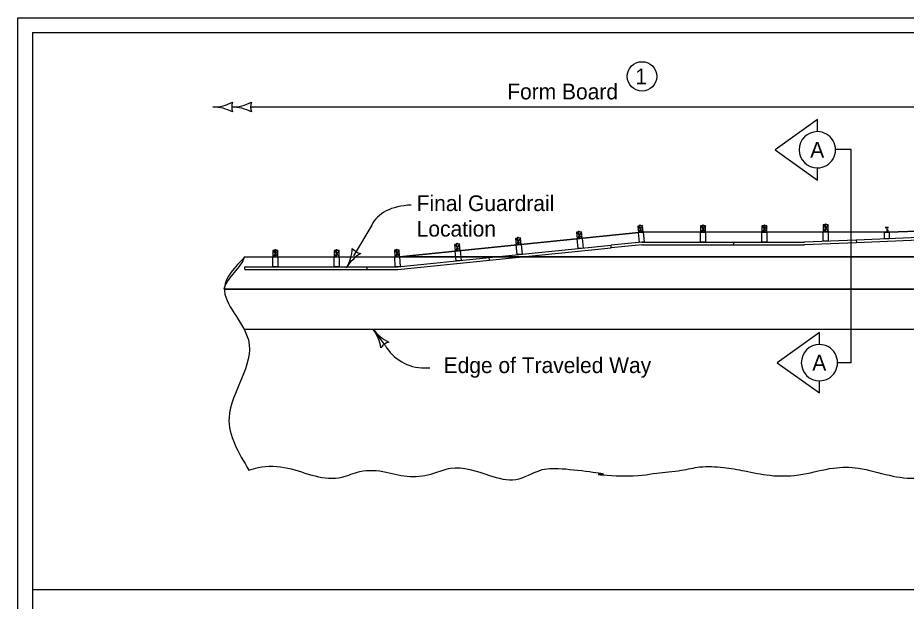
# Model space of a CAD drawing. Extents: x 9538 to 81668, y 7600 to 11751.
# Drawn here: x 17333 to 18239, y 9349 to 9944 of the extents above; entities that cross this region are included whole.
import ezdxf

# ---------------------------------------------------------------- set-up
doc = ezdxf.new("R2010")
doc.units = 0
for name, color, linetype in [('Default', 7, 'Continuous'), ('DsnShtMinorGrid13', 7, 'Continuous'), ('DsnShtMinorGrid14', 7, 'Continuous'), ('dsnStdCells', 7, 'Continuous'), ('dsnStdDimension', 7, 'Continuous'), ('dsnStdNameDate', 7, 'Continuous'), ('dsnStdNote', 7, 'Continuous'), ('dsnStdPattern', 7, 'Continuous'), ('dsnStdShading', 7, 'Continuous'), ('dsnStdTable', 7, 'Continuous')]:
    doc.layers.add(name, color=color, linetype=linetype)

msp = doc.modelspace()

# ---------------------------------------------------------------- linework, layer by layer
at = {"layer": 'Default'}
msp.add_lwpolyline([(17332.53, 9944.02), (20467.54, 9944.02), (20467.54, 7924.02), (17332.53, 7924.02)], close=True, dxfattribs=at)
at = {"layer": 'DsnShtMinorGrid13'}
msp.add_circle((17969.21, 9884.28), 15, dxfattribs=at)
at = {"layer": 'DsnShtMinorGrid14'}
for p, q in [((17969.82, 9732.2), (17965.51, 9725.07)), ((17967.24, 9732.92), (17967.23, 9732.99)), ((18031.5, 9733), (18031.5, 9733.07)), ((18094, 9733), (18094, 9733.07)), ((18154, 9732.89), (18159, 9726.23)), ((18159, 9732.89), (18154, 9726.23)), ((18156.5, 9733.86), (18156.5, 9733.93)), ((18156.5, 9726.23), (18156.5, 9732.89)), ((17902.38, 9725.42), (17908.03, 9719.29)), ((17907.36, 9725.92), (17903.05, 9718.79)), ((17904.77, 9726.64), (17904.77, 9726.71)), ((17905.54, 9719.04), (17904.87, 9725.67)), ((17964.85, 9731.7), (17970.49, 9725.56)), ((17965.51, 9725.07), (17970.49, 9725.56)), ((17968, 9725.32), (17965.51, 9725.07)), ((17968, 9725.32), (17965.51, 9725.07)), ((17966.51, 9715.11), (17965.51, 9725.07)), ((17968, 9725.32), (17967.34, 9731.95)), ((17970.49, 9725.56), (17971.49, 9715.61)), ((18029, 9732.03), (18034, 9725.37)), ((18034, 9732.03), (18029, 9725.37)), ((18029, 9725.37), (18034, 9725.37)), ((18029, 9715.36), (18029, 9725.37)), ((18031.5, 9725.37), (18031.5, 9732.03)), ((18034, 9725.37), (18034, 9715.36)), ((18091.5, 9732.03), (18096.5, 9725.37)), ((18096.5, 9732.03), (18091.5, 9725.37)), ((18091.5, 9725.37), (18096.5, 9725.37)), ((18091.5, 9715.36), (18091.5, 9725.37)), ((18094, 9725.37), (18094, 9732.03)), ((18096.5, 9725.37), (18096.5, 9715.36)), ((18154, 9726.23), (18159, 9726.23)), ((18154, 9716.22), (18154, 9726.23)), ((18159, 9726.23), (18159, 9716.22)), ((17780.41, 9714.18), (17780.4, 9714.25)), ((17840.2, 9719.17), (17845.84, 9713.04)), ((17845.17, 9719.67), (17840.86, 9712.54)), ((17842.59, 9720.39), (17842.58, 9720.46)), ((17843.35, 9712.79), (17842.68, 9719.42)), ((17903.05, 9718.79), (17908.03, 9719.29)), ((17904.05, 9708.83), (17903.05, 9718.79)), ((17908.03, 9719.29), (17909.03, 9709.33)), ((17969, 9715.36), (17937.63, 9712.2)), ((17971.49, 9715.61), (17966.51, 9715.11)), ((17969, 9715.36), (18062.75, 9715.36)), ((18034, 9715.36), (18029, 9715.36)), ((18062.75, 9712.64), (18062.75, 9715.36)), ((18062.75, 9715.36), (18134.98, 9715.36)), ((18062.75, 9712.65), (18062.75, 9715.36)), ((18096.5, 9715.36), (18091.5, 9715.36)), ((18159, 9716.22), (18154, 9716.22)), ((17592.75, 9706.96), (17597.75, 9700.29)), ((17597.75, 9706.96), (17592.75, 9700.29)), ((17595.25, 9707.93), (17595.25, 9708)), ((17595.25, 9700.29), (17595.25, 9706.96)), ((17655.25, 9706.96), (17660.25, 9700.29)), ((17660.25, 9706.96), (17655.25, 9700.29)), ((17657.75, 9707.93), (17657.75, 9708)), ((17657.75, 9700.29), (17657.75, 9706.96)), ((17716.64, 9707.02), (17721.97, 9700.58)), ((17721.64, 9707.27), (17716.97, 9700.33)), ((17719.09, 9708.12), (17719.09, 9708.19)), ((17719.47, 9700.45), (17719.14, 9707.15)), ((17778.02, 9712.96), (17783.66, 9706.79)), ((17782.99, 9713.46), (17778.68, 9706.29)), ((17778.68, 9706.29), (17783.66, 9706.79)), ((17779.68, 9696.28), (17778.68, 9706.29)), ((17781.17, 9706.54), (17780.51, 9713.21)), ((17783.66, 9706.79), (17784.66, 9696.78)), ((17813.26, 9699.7), (17937.63, 9712.2)), ((17813.53, 9697.01), (17937.91, 9709.51)), ((17840.86, 9712.54), (17845.84, 9713.04)), ((17841.86, 9702.58), (17840.86, 9712.54)), ((17845.84, 9713.04), (17846.84, 9703.08)), ((17909.03, 9709.33), (17904.05, 9708.83)), ((17937.91, 9709.51), (17937.63, 9712.2)), ((17937.9, 9709.52), (17937.63, 9712.2)), ((17969, 9712.65), (17937.9, 9709.52)), ((17969, 9712.65), (18062.75, 9712.65)), ((18062.75, 9712.65), (18135.01, 9712.65)), ((17592.75, 9700.29), (17597.76, 9700.29)), ((17592.75, 9690.28), (17592.75, 9700.29)), ((17597.76, 9700.29), (17597.76, 9690.28)), ((17655.25, 9700.29), (17660.26, 9700.29)), ((17655.25, 9690.28), (17655.25, 9700.29)), ((17660.26, 9700.29), (17660.26, 9690.28)), ((17716.97, 9700.33), (17721.97, 9700.58)), ((17717.47, 9690.28), (17716.97, 9700.33)), ((17719.98, 9690.28), (17813.26, 9699.7)), ((17720.25, 9687.57), (17813.53, 9697)), ((17721.97, 9700.58), (17722.47, 9690.53)), ((17784.66, 9696.78), (17779.68, 9696.28)), ((17813.53, 9697), (17813.26, 9699.7)), ((17813.53, 9697.01), (17813.26, 9699.7)), ((17846.84, 9703.08), (17841.86, 9702.58)), ((17564, 9690.28), (17689, 9690.28)), ((17564, 9687.57), (17564, 9690.28)), ((17564, 9687.57), (17689, 9687.57)), ((17597.76, 9690.28), (17592.75, 9690.28)), ((17660.26, 9690.28), (17655.25, 9690.28)), ((17689, 9690.28), (17719.98, 9690.28)), ((17689, 9687.57), (17689, 9690.28)), ((17689, 9687.57), (17720.25, 9687.57)), ((17722.47, 9690.53), (17717.47, 9690.28))]:
    msp.add_line(p, q, dxfattribs=at)
for points in [[(17965.51, 9725.07), (17970.49, 9725.56), (17969.82, 9732.2), (17964.85, 9731.7)], [(18154, 9726.23), (18159, 9726.23), (18159, 9732.89), (18154, 9732.89)], [(17903.05, 9718.79), (17908.03, 9719.29), (17907.36, 9725.92), (17902.38, 9725.42)], [(18029, 9725.37), (18034, 9725.37), (18034, 9732.03), (18029, 9732.03)], [(18091.5, 9725.37), (18096.5, 9725.37), (18096.5, 9732.03), (18091.5, 9732.03)], [(17840.86, 9712.54), (17845.84, 9713.04), (17845.17, 9719.67), (17840.2, 9719.17)], [(17592.75, 9700.29), (17597.75, 9700.29), (17597.75, 9706.96), (17592.75, 9706.96)], [(17655.25, 9700.29), (17660.25, 9700.29), (17660.25, 9706.96), (17655.25, 9706.96)], [(17716.97, 9700.33), (17721.97, 9700.58), (17721.64, 9707.27), (17716.64, 9707.02)], [(17778.68, 9706.29), (17783.66, 9706.79), (17782.99, 9713.46), (17778.02, 9712.96)]]:
    msp.add_lwpolyline(points, close=True, dxfattribs=at)
for points in [[(17967, 9731.92), (17966.96, 9732.34), (17967.62, 9732.41), (17967.67, 9731.98)], [(17967.1, 9732.36), (17967.05, 9732.9), (17967.43, 9732.94), (17967.49, 9732.4)], [(18031.16, 9732.03), (18031.16, 9732.46), (18031.83, 9732.46), (18031.83, 9732.03)], [(18031.3, 9732.46), (18031.3, 9733), (18031.69, 9733), (18031.69, 9732.46)], [(18093.66, 9732.03), (18093.66, 9732.46), (18094.33, 9732.46), (18094.33, 9732.03)], [(18093.8, 9732.46), (18093.8, 9733), (18094.19, 9733), (18094.19, 9732.46)], [(18156.16, 9732.89), (18156.16, 9733.32), (18156.83, 9733.32), (18156.83, 9732.89)], [(18156.3, 9733.32), (18156.3, 9733.86), (18156.69, 9733.86), (18156.69, 9733.32)], [(17904.54, 9725.64), (17904.5, 9726.07), (17905.16, 9726.13), (17905.2, 9725.7)], [(17904.63, 9726.08), (17904.58, 9726.62), (17904.97, 9726.66), (17905.02, 9726.12)], [(17780.27, 9713.62), (17780.22, 9714.16), (17780.6, 9714.2), (17780.66, 9713.66)], [(17842.35, 9719.39), (17842.31, 9719.82), (17842.97, 9719.88), (17843.02, 9719.45)], [(17842.45, 9719.83), (17842.39, 9720.37), (17842.78, 9720.41), (17842.84, 9719.87)], [(17594.92, 9706.96), (17594.92, 9707.39), (17595.58, 9707.39), (17595.58, 9706.96)], [(17595.06, 9707.39), (17595.06, 9707.93), (17595.45, 9707.93), (17595.45, 9707.39)], [(17657.42, 9706.96), (17657.42, 9707.39), (17658.08, 9707.39), (17658.08, 9706.96)], [(17657.56, 9707.39), (17657.56, 9707.93), (17657.95, 9707.93), (17657.95, 9707.39)], [(17718.81, 9707.13), (17718.78, 9707.56), (17719.45, 9707.59), (17719.47, 9707.16)], [(17718.92, 9707.57), (17718.9, 9708.11), (17719.28, 9708.13), (17719.31, 9707.59)], [(17780.18, 9713.17), (17780.13, 9713.61), (17780.8, 9713.67), (17780.84, 9713.24)], [(17719.47, 9700.45), (17716.97, 9700.33), (17716.97, 9700.33)]]:
    msp.add_lwpolyline(points, dxfattribs=at)
at = {"layer": 'dsnStdCells'}
for p, q in [((18216.44, 9718.72), (18216.44, 9725.68)), ((18216.44, 9725.68), (18217.07, 9725.68)), ((18217.07, 9725.37), (18217.07, 9725.68)), ((18220.82, 9725.37), (18217.07, 9725.37)), ((18220.71, 9730.26), (18217.38, 9730.26)), ((18217.38, 9730.26), (18217.38, 9730.1)), ((18217.38, 9730.26), (18217.38, 9730.1)), ((18220.71, 9730.26), (18217.38, 9730.26)), ((18217.38, 9730.1), (18218.55, 9730.1)), ((18217.38, 9730.1), (18218.55, 9730.1)), ((18218.55, 9725.52), (18217.38, 9725.52)), ((18217.38, 9725.52), (18217.38, 9725.37)), ((18217.38, 9725.52), (18217.38, 9725.37)), ((18218.55, 9725.52), (18217.38, 9725.52)), ((18217.38, 9725.37), (18220.71, 9725.37)), ((18217.38, 9725.37), (18220.71, 9725.37)), ((18218.97, 9729.69), (18218.97, 9725.94)), ((18218.97, 9729.69), (18218.97, 9725.94)), ((18219.12, 9725.94), (18219.12, 9729.69)), ((18219.12, 9725.94), (18219.12, 9729.69)), ((18219.36, 9726.04), (18219.28, 9725.99)), ((18219.36, 9726.04), (18219.28, 9725.99)), ((18219.28, 9725.99), (18219.28, 9725.61)), ((18219.28, 9725.61), (18219.28, 9725.99)), ((18219.36, 9726.04), (18220.33, 9726.04)), ((18220.33, 9726.04), (18219.36, 9726.04)), ((18219.54, 9730.1), (18220.71, 9730.1)), ((18219.54, 9730.1), (18220.71, 9730.1)), ((18220.71, 9725.52), (18219.54, 9725.52)), ((18220.71, 9725.52), (18219.54, 9725.52)), ((18219.58, 9725.99), (18219.58, 9725.57)), ((18219.58, 9725.57), (18219.58, 9725.99)), ((18219.58, 9725.57), (18219.58, 9725.99)), ((18220.14, 9727.55), (18219.62, 9727.55)), ((18219.62, 9727.55), (18219.62, 9726.04)), ((18220.14, 9727.55), (18219.62, 9727.55)), ((18219.62, 9727.55), (18219.62, 9726.04)), ((18219.62, 9726.04), (18220.14, 9726.04)), ((18220.14, 9726.04), (18220.14, 9727.55)), ((18220.14, 9726.04), (18220.14, 9727.55)), ((18220.18, 9725.57), (18220.18, 9725.99)), ((18220.18, 9725.99), (18220.18, 9725.57)), ((18220.18, 9725.57), (18220.18, 9725.99)), ((18220.33, 9726.04), (18220.4, 9726.04)), ((18220.4, 9726.04), (18220.33, 9726.04)), ((18220.48, 9725.99), (18220.4, 9726.04)), ((18220.48, 9725.99), (18220.4, 9726.04)), ((18220.4, 9725.52), (18220.48, 9725.57)), ((18220.4, 9725.52), (18220.48, 9725.57)), ((18220.48, 9725.57), (18220.48, 9725.99)), ((18220.48, 9725.57), (18220.48, 9725.99)), ((18220.71, 9730.1), (18220.71, 9730.26)), ((18220.71, 9730.1), (18220.71, 9730.26)), ((18220.71, 9725.37), (18220.71, 9725.52)), ((18220.71, 9725.37), (18220.71, 9725.52)), ((18220.82, 9725.68), (18221.44, 9725.68)), ((18220.82, 9725.68), (18220.82, 9725.37)), ((18221.44, 9725.68), (18221.44, 9718.72)), ((18221.44, 9718.72), (18216.44, 9718.72))]:
    msp.add_line(p, q, dxfattribs=at)
for points in [[(18219.28, 9725.61), (18219.28, 9725.61)], [(18219.54, 9725.52), (18220.4, 9725.52), (18220.4, 9725.52)]]:
    msp.add_lwpolyline(points, dxfattribs=at)
for centre, start, end in [((18218.55, 9729.69), 359.99336, 90.00253), ((18218.55, 9729.69), 359.99336, 90.00253), ((18218.55, 9725.94), 270.00734, 359.99635), ((18218.55, 9725.94), 270.00734, 359.99635), ((18219.54, 9729.69), 90.00734, 179.99635), ((18219.54, 9729.69), 90.00734, 179.99635), ((18219.54, 9725.94), 179.99336, 270.00253), ((18219.54, 9725.94), 179.99336, 270.00253), ((18219.54, 9725.94), 230.88662, 270.00253)]:
    msp.add_arc(centre, 0.417, start, end, dxfattribs=at)
for points in [[(18219.58, 9725.99), (18219.55, 9726), (18219.5, 9726.03), (18219.42, 9726.05), (18219.34, 9726.03), (18219.3, 9726), (18219.28, 9725.99)], [(18219.58, 9725.99), (18219.55, 9726), (18219.5, 9726.03), (18219.42, 9726.05), (18219.34, 9726.03), (18219.3, 9726), (18219.28, 9725.99)], [(18219.28, 9725.99), (18219.3, 9726), (18219.34, 9726.03), (18219.42, 9726.05), (18219.5, 9726.03), (18219.55, 9726), (18219.58, 9725.99)], [(18219.48, 9725.53), (18219.49, 9725.53), (18219.52, 9725.54), (18219.56, 9725.56), (18219.58, 9725.57)], [(18220.18, 9725.99), (18220.13, 9726), (18220.02, 9726.03), (18219.86, 9726.04), (18219.71, 9726.03), (18219.62, 9726), (18219.58, 9725.99)], [(18220.18, 9725.99), (18220.13, 9726), (18220.02, 9726.03), (18219.86, 9726.04), (18219.71, 9726.03), (18219.62, 9726), (18219.58, 9725.99)], [(18219.58, 9725.99), (18219.62, 9726), (18219.71, 9726.03), (18219.86, 9726.04), (18220.02, 9726.03), (18220.13, 9726), (18220.18, 9725.99)], [(18219.58, 9725.57), (18219.63, 9725.56), (18219.74, 9725.53), (18219.89, 9725.52), (18220.04, 9725.54), (18220.13, 9725.56), (18220.18, 9725.57)], [(18220.18, 9725.57), (18220.13, 9725.56), (18220.04, 9725.54), (18219.89, 9725.52), (18219.74, 9725.53), (18219.63, 9725.56), (18219.58, 9725.57)], [(18219.58, 9725.57), (18219.63, 9725.56), (18219.74, 9725.53), (18219.89, 9725.52), (18220.04, 9725.54), (18220.13, 9725.56), (18220.18, 9725.57)], [(18220.48, 9725.99), (18220.46, 9726), (18220.43, 9726.02), (18220.37, 9726.04), (18220.29, 9726.04), (18220.23, 9726.02), (18220.19, 9726), (18220.18, 9725.99)], [(18220.48, 9725.99), (18220.46, 9726), (18220.43, 9726.02), (18220.37, 9726.04), (18220.29, 9726.04), (18220.23, 9726.02), (18220.19, 9726), (18220.18, 9725.99)], [(18220.18, 9725.99), (18220.19, 9726), (18220.23, 9726.02), (18220.29, 9726.04), (18220.37, 9726.04), (18220.43, 9726.02), (18220.46, 9726), (18220.48, 9725.99)], [(18220.18, 9725.57), (18220.19, 9725.57), (18220.23, 9725.55), (18220.29, 9725.52), (18220.37, 9725.52), (18220.43, 9725.54), (18220.46, 9725.56), (18220.48, 9725.57)], [(18220.48, 9725.57), (18220.46, 9725.56), (18220.43, 9725.54), (18220.37, 9725.52), (18220.29, 9725.52), (18220.23, 9725.55), (18220.19, 9725.57), (18220.18, 9725.57)], [(18220.18, 9725.57), (18220.19, 9725.57), (18220.23, 9725.55), (18220.29, 9725.52), (18220.37, 9725.52), (18220.43, 9725.54), (18220.46, 9725.56), (18220.48, 9725.57)]]:
    msp.add_open_spline(points, degree=3, dxfattribs=at)
at = {"layer": 'dsnStdDimension'}
msp.add_line((17570.81, 9853.15), (18593.22, 9853.15), dxfattribs=at)
for centre, radius, start, end in [((17531.59, 9895.5), 42.5, 270, 298.07249), ((17531.59, 9810.5), 42.5, 61.92751, 90), ((17550.81, 9895.5), 42.5, 270, 298.07249), ((17567.22, 9853), 16.42, 162.26665, 197.73335), ((17550.81, 9810.5), 42.5, 61.92751, 90), ((17586.44, 9853), 16.42, 162.26665, 197.73335)]:
    msp.add_arc(centre, radius, start, end, dxfattribs=at)
at = {"layer": 'dsnStdNameDate'}
for p, q in [((18649.56, 9742.98), (18220.71, 9725.37)), ((17969.53, 9725.37), (17721.75, 9700.29)), ((18220.71, 9725.37), (17969.53, 9725.37)), ((17721.75, 9700.29), (18696.11, 9700.29)), ((18753.66, 9700.29), (17721.75, 9700.29)), ((19503.11, 9361.02), (17347.53, 9361.02))]:
    msp.add_line(p, q, dxfattribs=at)
at = {"layer": 'dsnStdNote'}
for p, q in [((17693.52, 9732.66), (17674.96, 9701.32)), ((17707.13, 9610.21), (17695.02, 9626.66)), ((17747.22, 9587.14), (17752.66, 9587.14))]:
    msp.add_line(p, q, dxfattribs=at)
for centre, radius, start, end in [((17631.2, 9710.82), 42.5, 329.37973, 357.45222), ((17685.93, 9719.84), 16.42, 221.64638, 257.11308), ((17704.35, 9667.53), 42.5, 121.30724, 149.37973), ((17729.24, 9651.86), 42.5, 216.37256, 244.44505), ((17660.8, 9601.45), 42.5, 8.30007, 36.37256), ((17716.15, 9597.97), 16.42, 108.63921, 144.10591), ((17747.27, 9633.6), 46.46, 210.22743, 270)]:
    msp.add_arc(centre, radius, start, end, dxfattribs=at)
msp.add_ellipse((17774.61, 9693.62), major_axis=(-81.09, 39.04), ratio=0.555556, start_param=5.482641, end_param=6.283185, dxfattribs=at)
at = {"layer": 'dsnStdPattern'}
for p, q in [((18182.62, 9809.76), (18166.85, 9809.76)), ((18182.62, 9592.47), (18182.62, 9809.76)), ((18182.62, 9592.47), (18168.67, 9592.47))]:
    msp.add_line(p, q, dxfattribs=at)
for points in [[(18148.06, 9827.94), (18148.06, 9840.26), (18104.92, 9809.45), (18148.06, 9778.64), (18148.06, 9790.97)], [(18150.18, 9610.96), (18150.18, 9623.28), (18107.05, 9592.47), (18150.18, 9561.66), (18150.18, 9573.99)]]:
    msp.add_lwpolyline(points, dxfattribs=at)
for centre, start, end in [((18148.06, 9809.45), 90.00083, 269.99917), ((18148.06, 9809.45), 269.99917, 90.00083), ((18150.18, 9592.47), 90.00083, 269.99917), ((18150.18, 9592.47), 269.99917, 90.00083)]:
    msp.add_arc(centre, 18.49, start, end, dxfattribs=at)
at = {"layer": 'dsnStdShading'}
for q in [(17347.53, 8319.02), (20443.23, 9929.02)]:
    msp.add_line((17347.53, 9929.02), q, dxfattribs=at)
at = {"layer": 'dsnStdTable'}
for p, q in [((18220.71, 9725.37), (18696.11, 9744.89)), ((18599.31, 9733.93), (18187.75, 9717.47)), ((17721.75, 9700.29), (17969.53, 9725.37)), ((18217.38, 9725.37), (17969.53, 9725.37)), ((18599.42, 9731.22), (18187.75, 9714.76)), ((18216.44, 9718.72), (18216.44, 9725.68)), ((18216.44, 9725.68), (18217.07, 9725.68)), ((18217.07, 9725.37), (18217.07, 9725.68)), ((18220.82, 9725.37), (18217.07, 9725.37)), ((18217.38, 9730.26), (18217.38, 9730.1)), ((18220.71, 9730.26), (18217.38, 9730.26)), ((18217.38, 9730.1), (18218.55, 9730.1)), ((18217.38, 9725.52), (18217.38, 9725.37)), ((18218.55, 9725.52), (18217.38, 9725.52)), ((18217.38, 9725.37), (18220.71, 9725.37)), ((18218.97, 9729.69), (18218.97, 9725.94)), ((18219.12, 9725.94), (18219.12, 9729.69)), ((18219.36, 9726.04), (18219.28, 9725.99)), ((18219.28, 9725.61), (18219.28, 9725.99)), ((18219.36, 9726.04), (18220.33, 9726.04)), ((18219.54, 9730.1), (18220.71, 9730.1)), ((18220.71, 9725.52), (18219.54, 9725.52)), ((18219.58, 9725.57), (18219.58, 9725.99)), ((18220.14, 9727.55), (18219.62, 9727.55)), ((18219.62, 9727.55), (18219.62, 9726.04)), ((18220.14, 9726.04), (18220.14, 9727.55)), ((18220.18, 9725.57), (18220.18, 9725.99)), ((18220.33, 9726.04), (18220.4, 9726.04)), ((18220.48, 9725.99), (18220.4, 9726.04)), ((18220.4, 9725.52), (18220.48, 9725.57)), ((18220.48, 9725.57), (18220.48, 9725.99)), ((18220.71, 9730.1), (18220.71, 9730.26)), ((18220.71, 9725.37), (18220.71, 9725.52)), ((18220.82, 9725.68), (18221.44, 9725.68)), ((18220.82, 9725.68), (18220.82, 9725.37)), ((18221.44, 9725.68), (18221.44, 9718.72)), ((18187.75, 9717.47), (18134.98, 9715.36)), ((18187.85, 9714.76), (18135.01, 9712.65)), ((18187.75, 9717.47), (18187.85, 9714.76)), ((18187.75, 9717.47), (18187.85, 9714.76)), ((18221.44, 9718.72), (18216.44, 9718.72)), ((17564, 9700.29), (17721.75, 9700.29)), ((17564, 9700.29), (18696.11, 9700.29)), ((17543, 9667.31), (19190.48, 9667.31)), ((18696.11, 9667.31), (17543, 9667.31)), ((17564.22, 9626.66), (19178.01, 9626.66))]:
    msp.add_line(p, q, dxfattribs=at)
for centre, start, end in [((18218.55, 9729.69), 359.99336, 90.00253), ((18218.55, 9725.94), 270.00734, 359.99635), ((18219.54, 9729.69), 90.00734, 179.99635), ((18219.54, 9725.94), 264.71743, 270.00253)]:
    msp.add_arc(centre, 0.417, start, end, dxfattribs=at)
for points in [[(18219.58, 9725.99), (18219.55, 9726), (18219.5, 9726.03), (18219.42, 9726.05), (18219.34, 9726.03), (18219.3, 9726), (18219.28, 9725.99)], [(18219.48, 9725.53), (18219.49, 9725.53), (18219.52, 9725.54), (18219.56, 9725.56), (18219.58, 9725.57)], [(18220.18, 9725.99), (18220.13, 9726), (18220.02, 9726.03), (18219.86, 9726.04), (18219.71, 9726.03), (18219.62, 9726), (18219.58, 9725.99)], [(18219.58, 9725.57), (18219.63, 9725.56), (18219.74, 9725.53), (18219.89, 9725.52), (18220.04, 9725.54), (18220.13, 9725.56), (18220.18, 9725.57)], [(18220.48, 9725.99), (18220.46, 9726), (18220.43, 9726.02), (18220.37, 9726.04), (18220.29, 9726.04), (18220.23, 9726.02), (18220.19, 9726), (18220.18, 9725.99)], [(18220.18, 9725.57), (18220.19, 9725.57), (18220.23, 9725.55), (18220.29, 9725.52), (18220.37, 9725.52), (18220.43, 9725.54), (18220.46, 9725.56), (18220.48, 9725.57)]]:
    msp.add_open_spline(points, degree=3, dxfattribs=at)
for points in [[(17564, 9700.29), (17543.35, 9668.74), (17567.71, 9615.65), (17548.01, 9536.55), (17568.29, 9482.94)], [(17543, 9667.31), (17543.35, 9668.74), (17545.04, 9672.81), (17547.45, 9676.73), (17553.51, 9684.34), (17559.66, 9692.04), (17563.19, 9698.15), (17564, 9700.29)], [(17568.29, 9482.94), (17577.72, 9485.52), (17607.94, 9484.95), (17635.88, 9476.96), (17663.25, 9475.82), (17681.5, 9481.53), (17708.3, 9480.96), (17732.82, 9476.39), (17756.77, 9479.81), (17773.87, 9484.95), (17813.79, 9477.53), (17840.59, 9473.54), (17865.11, 9482.67), (17887.92, 9484.38), (17926.7, 9478.67), (17926.12, 9478.67), (17947.28, 9477.07), (17984.35, 9479.92), (18009.44, 9482.78), (18028.25, 9486.2), (18052.2, 9485.63), (18073.87, 9482.21), (18099.53, 9477.64), (18133.18, 9478.78), (18164.54, 9485.06), (18189.63, 9485.06), (18221.56, 9477.64), (18250.64, 9474.79), (18284.29, 9481.63), (18316.79, 9485.06), (18351, 9478.21), (18376.66, 9475.36), (18398.9, 9478.78), (18426.84, 9494.19), (18437.11, 9496.47), (18461.63, 9498.75), (18492.29, 9499.32), (18513.39, 9499.32), (18566.7, 9490.03)]]:
    msp.add_spline(points, degree=3, dxfattribs=at)

# ---------------------------------------------------------------- texts
at = {"layer": 'DsnShtMinorGrid13'}
msp.add_text('1', height=16, dxfattribs=at).set_placement((17962.43, 9876.28))
at = {"layer": 'dsnStdDimension'}
msp.add_text('Form Board', height=16, dxfattribs=at).set_placement((17831.76, 9860.84))
at = {"layer": 'dsnStdNote'}
for s, p in [('Final Guardrail ', (17739.41, 9746.99)), ('Location', (17739.41, 9720.99)), ('Edge of Traveled Way', (17766.86, 9581.87))]:
    msp.add_text(s, height=16, dxfattribs=at).set_placement(p)
at = {"layer": 'dsnStdPattern'}
for p in [(18140.78, 9801.45), (18142.88, 9584.47)]:
    msp.add_text('A', height=16, dxfattribs=at).set_placement(p)

doc.saveas('drawing.dxf')
